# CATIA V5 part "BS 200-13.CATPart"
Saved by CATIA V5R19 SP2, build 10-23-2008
Part number: BS 200-13
Bounding box of the stored display mesh (mm): x -12.497 to 12.497, y -12.358 to 12.358, z 0 to 56
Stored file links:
  C:\Users\Bora\Desktop\3D Katı model\BS serisi\BS 200\BS 200-13.CATPart
  C:\Program Files\Dassault Systemes\B19\intel_a\reffiles\standard\MetricThickPitch.txt
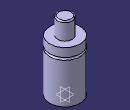
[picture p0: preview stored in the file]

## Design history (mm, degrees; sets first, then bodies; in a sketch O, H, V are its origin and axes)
Body1 (main body)
  Sketch1 on yz-plane, origin (0, 0, 0), H (0, 1, 0), V (0, 0, 1)
    point P1 (12.5, 35)
    point P4 (12.5, 33)
    point P5 (12.5, 35)
    point P6 (12.5, 33)
    point P7 (6, 55)
    point P9 (6, 55)
    line L1 (12.5, 35) -> (12.5, 42)
    line L2 (12.5, 0) -> (12.5, 33)
    arc A1 centre (12.5, 34) radius 1 from (12.5, 35) to (12.5, 33) ccw
    arc A2 centre (5, 55) radius 1 from (6, 55) to (5, 56) ccw
    line L3 (6, 55) -> (6, 42)
    line L4 (5, 56) -> (0, 56)
    point P11 (0, 56)
    line L5 (6, 42) -> (12.5, 42)
    line L6 (12.5, 0) -> (0, 0)
    coincidence: P11 V, P1 P5, P4 P6, P7 P9
    tangency: L4 A2
    horizontal: L5 H, L6 H
  Shaft1: profile Sketch1, axis Sketch1.V, angle 360
  Sketch2 on face of Shaft1 from Sketch1.L6, origin (0, 0, 0), H (1, 0, 0), V (0, -1, 0)
    point P1 (0, 0)
  Hole1: placed by Sketch2, at (0, 0, 0) direction (0, 0, 1), diameter 4.917, depth 4, threaded "M6", thread diameter 6, thread depth 4, pitch 1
